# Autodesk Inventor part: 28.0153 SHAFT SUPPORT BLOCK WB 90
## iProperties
Created: 2007-06
Part Number: 28.0153 SHAFT SUPPORT BLOCK WB 90
Document SubType Name: Modeling
Designer: Andy Moles
Material: Aluminum-6061
Mass: 344.118 g
Surface Area: 707.042 cm^2
Volume: 126.981 cm^3
Density: 2.71 g/cm^3
Author: Andy Moles
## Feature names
1. Extrusion1
2. Extrusion2
